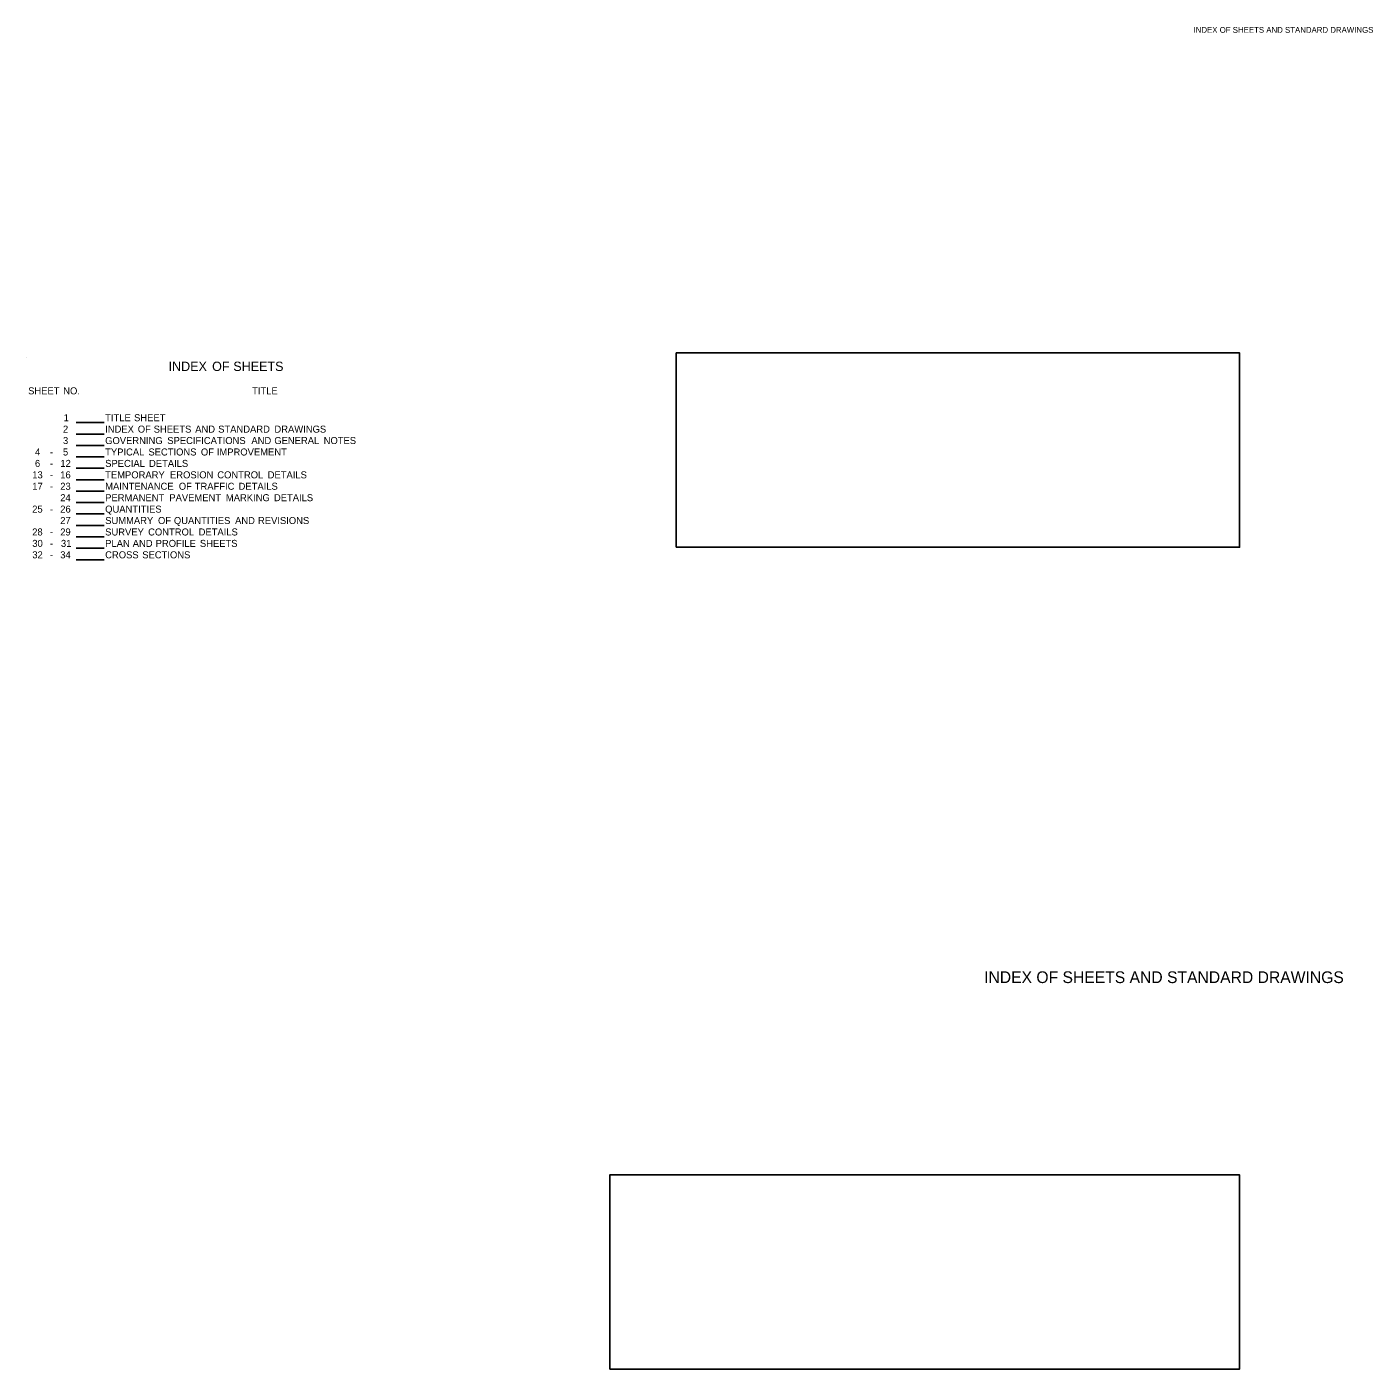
# Model space of a CAD drawing. Extents: x 273 to 1651, y -357 to 1017.
import ezdxf

# ---------------------------------------------------------------- set-up
doc = ezdxf.new("R2010")
doc.units = 0
for name, color, linetype in [('Default', 7, 'Continuous'), ('R_Annotation', 7, 'Continuous'), ('R_Border', 7, 'Continuous'), ('R_No Plot', 7, 'Continuous')]:
    doc.layers.add(name, color=color, linetype=linetype)

msp = doc.modelspace()

# ---------------------------------------------------------------- linework, layer by layer
at = {"layer": 'Default'}
for p, q in [((323, 611.7), (351.7, 611.7)), ((323, 600), (351.7, 600)), ((323, 588.3), (351.7, 588.3)), ((323, 576.6), (351.7, 576.6)), ((323, 564.9), (351.7, 564.9)), ((323, 553.2), (351.7, 553.2)), ((323, 541.5), (351.7, 541.5)), ((323, 529.8), (351.7, 529.8)), ((323, 518.1), (351.7, 518.1)), ((323, 506.4), (351.7, 506.4)), ((323, 494.7), (351.7, 494.7)), ((323, 483), (351.7, 483)), ((323, 471.3), (351.7, 471.3))]:
    msp.add_line(p, q, dxfattribs=at)
at = {"layer": 'R_No Plot'}
msp.add_line((272.7, 678.4), (272.7, 678.4), dxfattribs=at)
for points in [[(937.5, 484.1), (1514.2, 484.1), (1514.2, 683), (937.5, 683)], [(869.3, -357.5), (1514.2, -357.5), (1514.2, -158.6), (869.3, -158.6)]]:
    msp.add_lwpolyline(points, close=True, dxfattribs=at)

# ---------------------------------------------------------------- texts
at = {"layer": 'Default'}
for s, height, p in [('INDEX', 9.6, (417.7, 664.5)), (' OF', 9.6, (458.7, 664.5)), (' SHEETS', 9.6, (480.4, 664.5)), ('SHEET', 7.2, (273.9, 640.6)), (' NO.', 7.2, (307.2, 640.6)), ('TITLE', 7.2, (503.2, 640.6)), ('1', 7.2, (310.3, 613.1)), ('TITLE', 7.2, (352.8, 613.1)), (' SHEET', 7.2, (379.7, 613.1)), ('2', 7.2, (309.6, 601.4)), ('INDEX', 7.2, (352.8, 601.4)), (' OF', 7.2, (383.5, 601.4)), (' SHEETS', 7.2, (399.8, 601.4)), (' AND', 7.2, (442.3, 601.4)), (' STANDARD', 7.2, (465.8, 601.4)), (' DRAWINGS', 7.2, (523.4, 601.4)), ('3', 7.2, (309.6, 589.7)), ('GOVERNING', 7.2, (352.8, 589.7)), (' SPECIFICATIONS', 7.2, (413.7, 589.7)), (' AND', 7.2, (499.8, 589.7)), (' GENERAL', 7.2, (523.3, 589.7)), (' NOTES', 7.2, (573.8, 589.7)), ('4', 7.2, (281, 578)), ('-', 7.2, (296.3, 578)), ('5', 7.2, (309.6, 578)), ('TYPICAL', 7.2, (352.8, 578)), (' SECTIONS', 7.2, (394.4, 578)), (' OF', 7.2, (448.1, 578)), (' IMPROVEMENT', 7.2, (464.4, 578)), ('6', 7.2, (280.9, 566.3)), ('-', 7.2, (296.3, 566.3)), ('12', 7.2, (306.9, 566.3)), ('SPECIAL', 7.2, (352.8, 566.3)), (' DETAILS', 7.2, (395, 566.3)), ('13', 7.2, (278.2, 554.6)), ('-', 7.2, (296.3, 554.6)), ('16', 7.2, (306.8, 554.6)), ('TEMPORARY', 7.2, (352.8, 554.6)), (' EROSION', 7.2, (416.5, 554.6)), (' CONTROL', 7.2, (464.9, 554.6)), (' DETAILS', 7.2, (516.5, 554.6)), ('17', 7.2, (278.2, 542.9)), ('-', 7.2, (296.3, 542.9)), ('23', 7.2, (306.8, 542.9)), ('24', 7.2, (306.8, 531.2)), ('MAINTENANCE', 7.2, (352.8, 542.9)), ('PERMANENT', 7.2, (352.8, 531.2)), (' PAVEMENT', 7.2, (415.8, 531.2)), (' OF', 7.2, (425.5, 542.9)), (' TRAFFIC', 7.2, (441.8, 542.9)), (' MARKING', 7.2, (473.7, 531.2)), (' DETAILS', 7.2, (486.7, 542.9)), (' DETAILS', 7.2, (522.9, 531.2)), ('25', 7.2, (278.1, 519.5)), ('26', 7.2, (306.8, 519.5)), ('QUANTITIES', 7.2, (352.8, 519.5)), ('-', 7.2, (296.3, 519.5)), ('27', 7.2, (306.8, 507.8)), ('SUMMARY', 7.2, (352.8, 507.8)), (' OF', 7.2, (404.2, 507.8)), (' QUANTITIES', 7.2, (420.5, 507.8)), (' AND', 7.2, (483.1, 507.8)), (' REVISIONS', 7.2, (506.6, 507.8)), ('28', 7.2, (278.1, 496.1)), ('-', 7.2, (296.3, 496.1)), ('29', 7.2, (306.8, 496.1)), ('SURVEY', 7.2, (352.8, 496.1)), (' CONTROL', 7.2, (394.1, 496.1)), (' DETAILS', 7.2, (445.8, 496.1)), ('30', 7.2, (278.2, 484.4)), ('-', 7.2, (296.3, 484.4)), ('31', 7.2, (307.5, 484.4)), ('PLAN', 7.2, (352.8, 484.4)), (' AND', 7.2, (378.3, 484.4)), (' PROFILE', 7.2, (401.8, 484.4)), (' SHEETS', 7.2, (447.1, 484.4)), ('32', 7.2, (278.2, 472.7)), ('-', 7.2, (296.3, 472.7)), ('34', 7.2, (306.8, 472.7)), ('CROSS', 7.2, (352.8, 472.7)), (' SECTIONS', 7.2, (388.1, 472.7))]:
    msp.add_text(s, height=height, dxfattribs=at).set_placement(p)
at = {"layer": 'R_Annotation'}
msp.add_text('INDEX OF SHEETS AND STANDARD DRAWINGS', height=12, dxfattribs=at).set_placement((1252.6, 37.8))
at = {"layer": 'R_Border'}
msp.add_text('INDEX OF SHEETS AND STANDARD DRAWINGS', height=6, dxfattribs=at).set_placement((1467, 1010.8))

doc.saveas('drawing.dxf')
